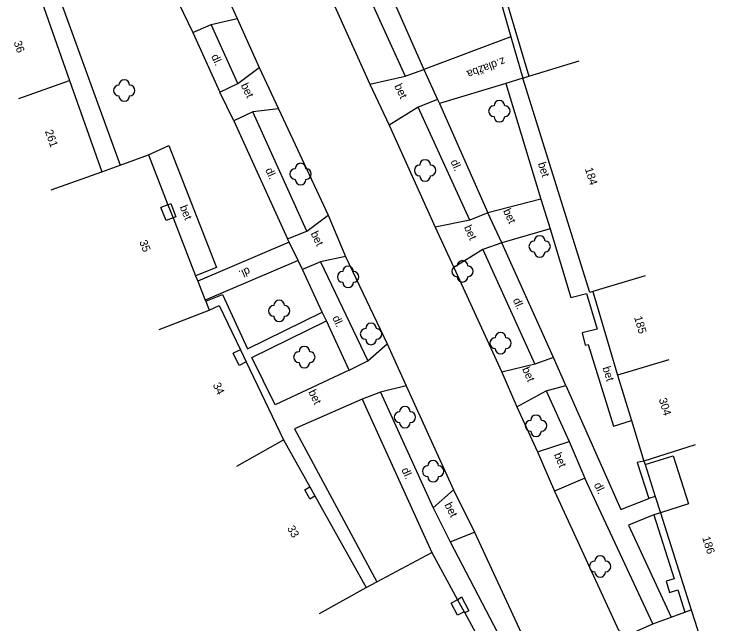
# Model space of a CAD drawing. Extents: x -544674 to -541478, y -1199076 to -1195527.
# Drawn here: x -542590.4 to -542525, y -1198800 to -1198743.1 of the extents above; entities that cross this region are included whole.
import ezdxf

# ---------------------------------------------------------------- set-up
doc = ezdxf.new("R2010")
doc.units = 0
for name, color, linetype in [('BUDOVY_MĚŘ', 7, 'Continuous'), ('POMOC_POPIS', 7, 'Continuous'), ('ROZHRANÍ_PLOCH', 7, 'Continuous'), ('ZELEŇ', 7, 'Continuous'), ('Č_POPIS_ORIENT', 7, 'Continuous')]:
    doc.layers.add(name, color=color, linetype=linetype)

msp = doc.modelspace()

# ---------------------------------------------------------------- linework, layer by layer
at = {"layer": 'BUDOVY_MĚŘ'}
for points in [[(-542547.97, -1198730.12), (-542542.37, -1198748.94)], [(-542588.2, -1198740.82), (-542585.22, -1198749.33)], [(-542542.37, -1198748.94), (-542537.67, -1198747.51)], [(-542589.93, -1198751), (-542585.22, -1198749.33)], [(-542585.22, -1198749.33), (-542582.21, -1198757.85)], [(-542542.94, -1198749.11), (-542542.37, -1198748.94)], [(-542536.4, -1198769.02), (-542536.69, -1198769.11), (-542542.94, -1198749.11)], [(-542580.5, -1198757.23), (-542577.86, -1198756.28)], [(-542577.86, -1198756.28), (-542576.04, -1198760.92)], [(-542582.21, -1198757.85), (-542580.5, -1198757.23)], [(-542586.92, -1198759.52), (-542582.21, -1198757.85)], [(-542576.04, -1198760.92), (-542575.56, -1198762.15)], [(-542575.56, -1198762.15), (-542573.45, -1198767.54)], [(-542573.45, -1198767.54), (-542573.25, -1198768.04)], [(-542531.53, -1198767.55), (-542536.4, -1198769.02)], [(-542573.25, -1198768.04), (-542572.55, -1198769.82)], [(-542536.4, -1198769.02), (-542534.09, -1198776.81)], [(-542572.55, -1198769.82), (-542572.51, -1198769.92)], [(-542572.51, -1198769.92), (-542572.19, -1198770.74)], [(-542572.19, -1198770.74), (-542571.26, -1198770.31), (-542569.28, -1198774.44)], [(-542576.85, -1198772.57), (-542572.19, -1198770.74)], [(-542569.28, -1198774.44), (-542568.73, -1198775.58)], [(-542568.73, -1198775.58), (-542565.25, -1198782.85)], [(-542529.3, -1198775.39), (-542534.09, -1198776.81)], [(-542534.09, -1198776.81), (-542532.79, -1198781.04)], [(-542532.79, -1198781.04), (-542531.63, -1198784.82)], [(-542569.61, -1198785.29), (-542565.25, -1198782.85)], [(-542565.25, -1198782.85), (-542562.79, -1198787.24)], [(-542526.87, -1198783.3), (-542531.63, -1198784.82)], [(-542531.63, -1198784.82), (-542531.52, -1198785.15)], [(-542531.52, -1198785.15), (-542530.58, -1198788.12)], [(-542562.79, -1198787.24), (-542562.32, -1198788.08)], [(-542562.32, -1198788.08), (-542557.55, -1198796.61)], [(-542530.58, -1198788.12), (-542530.1, -1198789.64)], [(-542530.1, -1198789.64), (-542527.22, -1198798.68)], [(-542556.54, -1198796.07), (-542551.41, -1198793.34)], [(-542551.41, -1198793.34), (-542549.02, -1198797.75)], [(-542557.55, -1198796.61), (-542556.54, -1198796.07)], [(-542561.91, -1198799.05), (-542557.55, -1198796.61)], [(-542549.02, -1198797.75), (-542548.41, -1198798.87)], [(-542548.41, -1198798.87), (-542548.34, -1198798.99)], [(-542548.34, -1198798.99), (-542544.49, -1198806.08)], [(-542527.22, -1198798.68), (-542526.08, -1198802.26)]]:
    msp.add_lwpolyline(points, dxfattribs=at)
at = {"layer": 'ROZHRANÍ_PLOCH'}
for points in [[(-542548.33, -1198730.23), (-542544.04, -1198745.26)], [(-542558.81, -1198733.2), (-542552.17, -1198748.31)], [(-542560.74, -1198733.88), (-542553.91, -1198748.94)], [(-542563.49, -1198735.71), (-542557.21, -1198749.67)], [(-542577.39, -1198737.16), (-542586.61, -1198740.35), (-542580.5, -1198757.23)], [(-542571.3, -1198739.8), (-542569.57, -1198743.55)], [(-542575.06, -1198742.1), (-542573.72, -1198744.87)], [(-542572, -1198744.1), (-542569.57, -1198743.55)], [(-542569.57, -1198743.55), (-542567.54, -1198748.13)], [(-542573.72, -1198744.87), (-542572, -1198744.1)], [(-542569.51, -1198749.62), (-542572, -1198744.1)], [(-542573.72, -1198744.87), (-542571.21, -1198750.41)], [(-542544.04, -1198745.26), (-542552.17, -1198748.31)], [(-542544.04, -1198745.26), (-542542.94, -1198749.11)], [(-542569.51, -1198749.62), (-542567.54, -1198748.13)], [(-542567.54, -1198748.13), (-542565.73, -1198751.98)], [(-542553.91, -1198748.94), (-542552.17, -1198748.31)], [(-542552.17, -1198748.31), (-542550.88, -1198751.12)], [(-542557.21, -1198749.67), (-542553.91, -1198748.94)], [(-542542.94, -1198749.11), (-542544.52, -1198749.62)], [(-542571.21, -1198750.41), (-542569.51, -1198749.62)], [(-542557.21, -1198749.67), (-542555.4, -1198753.49)], [(-542544.52, -1198749.62), (-542550.72, -1198751.49)], [(-542544.52, -1198749.62), (-542541.24, -1198760.39)], [(-542569.9, -1198753.1), (-542571.21, -1198750.41)], [(-542550.88, -1198751.12), (-542552.69, -1198751.82)], [(-542550.88, -1198751.12), (-542550.72, -1198751.49)], [(-542565.73, -1198751.98), (-542568.12, -1198752.27)], [(-542565.73, -1198751.98), (-542561.09, -1198761.88)], [(-542552.69, -1198751.82), (-542555.4, -1198753.49)], [(-542547.87, -1198762.35), (-542552.69, -1198751.82)], [(-542550.72, -1198751.49), (-542546.2, -1198761.69)], [(-542568.12, -1198752.27), (-542569.9, -1198753.1)], [(-542563.09, -1198763.39), (-542568.12, -1198752.27)], [(-542569.9, -1198753.1), (-542564.88, -1198764.1)], [(-542555.4, -1198753.49), (-542551.1, -1198763.01)], [(-542577.86, -1198756.28), (-542575.94, -1198755.41), (-542571.49, -1198766.77), (-542573.45, -1198767.54)], [(-542541.24, -1198760.39), (-542546.2, -1198761.69)], [(-542541.24, -1198760.39), (-542540.39, -1198763.17)], [(-542576.04, -1198760.92), (-542576.69, -1198761.17)], [(-542576.21, -1198762.4), (-542576.69, -1198761.17)], [(-542576.04, -1198760.92), (-542575.78, -1198760.81), (-542575.31, -1198762.05), (-542575.56, -1198762.15)], [(-542546.2, -1198761.69), (-542547.87, -1198762.35)], [(-542544.9, -1198764.46), (-542546.2, -1198761.69)], [(-542575.56, -1198762.15), (-542576.21, -1198762.4)], [(-542563.09, -1198763.39), (-542561.09, -1198761.88)], [(-542561.09, -1198761.88), (-542559.46, -1198765.76)], [(-542547.87, -1198762.35), (-542551.1, -1198763.01)], [(-542551.1, -1198763.01), (-542549.38, -1198766.77)], [(-542540.39, -1198763.17), (-542544.9, -1198764.46)], [(-542540.39, -1198763.17), (-542538.44, -1198769.58), (-542536.98, -1198769.19), (-542536.01, -1198772.51), (-542537.41, -1198772.87), (-542537.13, -1198774.01), (-542536.84, -1198773.94), (-542534.47, -1198781.56), (-542532.79, -1198781.04)], [(-542564.88, -1198764.1), (-542563.09, -1198763.39)], [(-542564.73, -1198764.41), (-542573.25, -1198768.04)], [(-542564.73, -1198764.41), (-542564.88, -1198764.1)], [(-542563.88, -1198766.12), (-542564.73, -1198764.41)], [(-542544.9, -1198764.46), (-542546.66, -1198765.1)], [(-542540.06, -1198775.16), (-542544.9, -1198764.46)], [(-542546.66, -1198765.1), (-542549.38, -1198766.77)], [(-542546.66, -1198765.1), (-542541.82, -1198775.78)], [(-542559.46, -1198765.76), (-542561.79, -1198766.26)], [(-542559.46, -1198765.76), (-542555.58, -1198773.89)], [(-542563.88, -1198766.12), (-542572.55, -1198769.82)], [(-542563.47, -1198766.95), (-542563.88, -1198766.12)], [(-542561.79, -1198766.26), (-542563.47, -1198766.95)], [(-542561.79, -1198766.26), (-542557.4, -1198775.49)], [(-542561.64, -1198770.94), (-542563.47, -1198766.95)], [(-542549.38, -1198766.77), (-542544.9, -1198776.53)], [(-542572.51, -1198769.92), (-542570.94, -1198769.3), (-542568.6, -1198774.35), (-542561.64, -1198770.94)], [(-542561.24, -1198771.76), (-542561.64, -1198770.94)], [(-542559.13, -1198776.35), (-542566.03, -1198779.57), (-542568.2, -1198775.17), (-542561.24, -1198771.76)], [(-542559.13, -1198776.35), (-542561.24, -1198771.76)], [(-542557.4, -1198775.49), (-542555.58, -1198773.89)], [(-542555.58, -1198773.89), (-542553.82, -1198777.82)], [(-542569.28, -1198774.44), (-542569.95, -1198774.76)], [(-542569.4, -1198775.9), (-542569.95, -1198774.76)], [(-542568.73, -1198775.58), (-542569.4, -1198775.9)], [(-542559.13, -1198776.35), (-542557.4, -1198775.49)], [(-542540.06, -1198775.16), (-542541.82, -1198775.78)], [(-542538.91, -1198777.77), (-542540.06, -1198775.16)], [(-542541.82, -1198775.78), (-542544.9, -1198776.53)], [(-542544.9, -1198776.53), (-542543.48, -1198779.78)], [(-542553.82, -1198777.82), (-542556.22, -1198778.39)], [(-542553.82, -1198777.82), (-542549.4, -1198787.52)], [(-542540.74, -1198778.28), (-542538.91, -1198777.77)], [(-542538.91, -1198777.77), (-542533.78, -1198789.35), (-542531.19, -1198788.32)], [(-542556.22, -1198778.39), (-542557.93, -1198779.06)], [(-542556.22, -1198778.39), (-542551.28, -1198789.17)], [(-542543.48, -1198779.78), (-542540.74, -1198778.28)], [(-542540.74, -1198778.28), (-542538.62, -1198782.99)], [(-542557.93, -1198779.06), (-542564.22, -1198781.82), (-542556.54, -1198796.07)], [(-542557.93, -1198779.06), (-542551.41, -1198793.34)], [(-542543.48, -1198779.78), (-542541.57, -1198783.97)], [(-542541.57, -1198783.97), (-542538.62, -1198782.99)], [(-542538.62, -1198782.99), (-542537.14, -1198786.43)], [(-542541.57, -1198783.97), (-542539.99, -1198787.62)], [(-542531.52, -1198785.15), (-542528.91, -1198784.32), (-542527.49, -1198788.81), (-542530.1, -1198789.64)], [(-542531.63, -1198784.82), (-542532.26, -1198784.95), (-542531.19, -1198788.32)], [(-542537.14, -1198786.43), (-542539.99, -1198787.62)], [(-542530.82, -1198800), (-542537.14, -1198786.43)], [(-542563.28, -1198787.51), (-542562.79, -1198787.24)], [(-542562.8, -1198788.35), (-542563.28, -1198787.51)], [(-542551.28, -1198789.17), (-542549.4, -1198787.52)], [(-542549.4, -1198787.52), (-542547.44, -1198791.44)], [(-542539.99, -1198787.62), (-542533.99, -1198800.65)], [(-542562.8, -1198788.35), (-542562.32, -1198788.08)], [(-542530.58, -1198788.12), (-542531.19, -1198788.32)], [(-542551.28, -1198789.17), (-542549.71, -1198792.34)], [(-542530.71, -1198789.85), (-542533.09, -1198790.8), (-542529.11, -1198799.37)], [(-542530.1, -1198789.64), (-542530.71, -1198789.85)], [(-542530.71, -1198789.85), (-542528.81, -1198795.79), (-542529.56, -1198796.03), (-542529.26, -1198797.07), (-542528.48, -1198796.82), (-542527.82, -1198798.9)], [(-542549.71, -1198792.34), (-542547.44, -1198791.44)], [(-542547.44, -1198791.44), (-542542.86, -1198801.31)], [(-542549.71, -1198792.34), (-542544.54, -1198802.24)], [(-542549.02, -1198797.75), (-542549.63, -1198798.08)], [(-542549.02, -1198797.75), (-542548.64, -1198797.49), (-542547.96, -1198798.78), (-542548.34, -1198798.99)], [(-542549.02, -1198799.2), (-542549.63, -1198798.08)], [(-542548.41, -1198798.87), (-542549.02, -1198799.2)], [(-542529.11, -1198799.37), (-542527.82, -1198798.9)], [(-542527.82, -1198798.9), (-542527.22, -1198798.68)], [(-542530.82, -1198800), (-542529.11, -1198799.37)], [(-542533.99, -1198800.65), (-542532.84, -1198800.89), (-542530.82, -1198800)]]:
    msp.add_lwpolyline(points, dxfattribs=at)
at = {"layer": 'ZELEŇ'}
for centre in [(-542580.11, -1198750.27), (-542545.12, -1198752.2), (-542552.05, -1198757.72), (-542563.66, -1198758.06), (-542541.36, -1198764.81), (-542559.23, -1198767.65), (-542548.56, -1198767.13), (-542565.66, -1198770.82), (-542557.09, -1198772.97), (-542545.01, -1198773.83), (-542563.31, -1198775.13), (-542553.93, -1198780.73), (-542541.7, -1198781.53), (-542551.3, -1198785.77), (-542535.72, -1198794.65)]:
    msp.add_circle(centre, 0.0005, dxfattribs=at)
for centre, start, end in [((-542580.11, -1198749.77), 0, 179.99999), ((-542580.61, -1198750.27), 89.99999, 269.99999), ((-542579.61, -1198750.27), 270, 89.99999), ((-542580.11, -1198750.77), 179.99999, 359.99999), ((-542545.12, -1198751.7), 0, 179.99999), ((-542545.62, -1198752.2), 89.99999, 269.99999), ((-542544.62, -1198752.2), 270, 89.99999), ((-542545.12, -1198752.7), 179.99999, 359.99999), ((-542563.66, -1198757.56), 0, 179.99999), ((-542552.55, -1198757.72), 89.99999, 269.99999), ((-542552.05, -1198757.22), 0, 179.99999), ((-542551.55, -1198757.72), 270, 89.99999), ((-542564.16, -1198758.06), 89.99999, 269.99999), ((-542563.16, -1198758.06), 270, 89.99999), ((-542563.66, -1198758.56), 179.99999, 359.99999), ((-542552.05, -1198758.22), 179.99999, 359.99999), ((-542541.36, -1198764.31), 0, 179.99999), ((-542541.86, -1198764.81), 89.99999, 269.99999), ((-542540.86, -1198764.81), 270, 89.99999), ((-542541.36, -1198765.31), 179.99999, 359.99999), ((-542548.56, -1198766.63), 0, 179.99999), ((-542559.23, -1198767.15), 0, 179.99999), ((-542549.06, -1198767.13), 89.99999, 269.99999), ((-542548.06, -1198767.13), 270, 89.99999), ((-542559.73, -1198767.65), 89.99999, 269.99999), ((-542558.73, -1198767.65), 270, 89.99999), ((-542548.56, -1198767.63), 179.99999, 359.99999), ((-542559.23, -1198768.15), 179.99999, 359.99999), ((-542566.16, -1198770.82), 89.99999, 269.99999), ((-542565.66, -1198770.32), 0, 179.99999), ((-542565.16, -1198770.82), 270, 89.99999), ((-542565.66, -1198771.32), 179.99999, 359.99999), ((-542557.09, -1198772.47), 0, 179.99999), ((-542557.59, -1198772.97), 89.99999, 269.99999), ((-542556.59, -1198772.97), 270, 89.99999), ((-542545.01, -1198773.33), 0, 179.99999), ((-542557.09, -1198773.47), 179.99999, 359.99999), ((-542545.51, -1198773.83), 89.99999, 269.99999), ((-542544.51, -1198773.83), 270, 89.99999), ((-542563.31, -1198774.63), 0, 179.99999), ((-542563.81, -1198775.13), 89.99999, 269.99999), ((-542562.81, -1198775.13), 270, 89.99999), ((-542545.01, -1198774.33), 179.99999, 359.99999), ((-542563.31, -1198775.63), 179.99999, 359.99999), ((-542553.93, -1198780.23), 0, 179.99999), ((-542554.43, -1198780.73), 89.99999, 269.99999), ((-542553.43, -1198780.73), 270, 89.99999), ((-542541.7, -1198781.03), 0, 179.99999), ((-542553.93, -1198781.23), 179.99999, 359.99999), ((-542542.2, -1198781.53), 89.99999, 269.99999), ((-542541.2, -1198781.53), 270, 89.99999), ((-542541.7, -1198782.03), 179.99999, 359.99999), ((-542551.8, -1198785.77), 89.99999, 269.99999), ((-542551.3, -1198785.27), 0, 179.99999), ((-542550.8, -1198785.77), 270, 89.99999), ((-542551.3, -1198786.27), 179.99999, 359.99999), ((-542535.72, -1198794.15), 0, 179.99999), ((-542536.22, -1198794.65), 89.99999, 269.99999), ((-542535.22, -1198794.65), 270, 89.99999), ((-542535.72, -1198795.15), 179.99999, 359.99999)]:
    msp.add_arc(centre, 0.5, start, end, dxfattribs=at)

# ---------------------------------------------------------------- texts
at = {"layer": 'POMOC_POPIS'}
for s, rotation, p in [('dl.', 294.37002, (-542572.02, -1198747.07)), ('z.dlažba', 200.59, (-542544.73, -1198747.15)), ('bet', 295.97, (-542569.26, -1198749.78)), ('bet', 295.35, (-542554.93, -1198749.84)), ('dl.', 294.6, (-542549.7, -1198756.9)), ('bet', 286.94001, (-542541.53, -1198757.07)), ('dl.', 294.52999, (-542566.98, -1198757.67)), ('bet', 291.41, (-542574.95, -1198761.12)), ('bet', 295.14001, (-542544.79, -1198761.49)), ('bet', 294.58001, (-542548.44, -1198763.02)), ('bet', 295.97, (-542562.75, -1198763.6)), ('dl.', 203.08002, (-542568.54, -1198766.71)), ('dl.', 294.37999, (-542543.88, -1198769.8)), ('dl.', 294.69001, (-542560.72, -1198771.45)), ('bet', 293.60002, (-542543.01, -1198776.23)), ('bet', 287.26998, (-542535.51, -1198776.12)), ('bet', 295.61001, (-542562.95, -1198778.37)), ('bet', 293.41003, (-542540.05, -1198784.22)), ('dl.', 294.54001, (-542554.28, -1198785.63)), ('dl.', 294.97002, (-542536.32, -1198787.02)), ('bet', 296.57, (-542550.26, -1198788.9))]:
    msp.add_text(s, height=0.75, rotation=rotation, dxfattribs=at).set_placement(p)
at = {"layer": 'Č_POPIS_ORIENT'}
for s, rotation, p in [('36', 289.30003, (-542590.44, -1198745.78)), ('261', 289.46, (-542587.52, -1198754.07)), ('184', 287.35002, (-542537.15, -1198757.57)), ('35', 291.41, (-542578.72, -1198764.37)), ('185', 286.53997, (-542532.56, -1198771.42)), ('34', 295.61001, (-542571.87, -1198777.71)), ('304', 287.07002, (-542530.26, -1198779.06)), ('33', 299.23002, (-542564.94, -1198791.08)), ('186', 287.65002, (-542526.21, -1198791.97))]:
    msp.add_text(s, height=0.75, rotation=rotation, dxfattribs=at).set_placement(p)

doc.saveas('drawing.dxf')
